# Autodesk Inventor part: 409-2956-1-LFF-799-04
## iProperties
Created: 2010-11
Part Number: 409-2956-1-LFF-799-04
Material: 3/4" OD TUBE - SS
Document SubType Name: Modeling
Designer: S. Boerckel
Engineer: Steve Boerckel
Mass: 731.966 g
Surface Area: 1099.2 cm^2
Volume: 90.5898 cm^3
Density: 8.08 g/cm^3
Description: DRAIN TUBING
Length: 39.223 in
Author: S. Boerckel
Revision Number: 0
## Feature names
1. Sweep2
